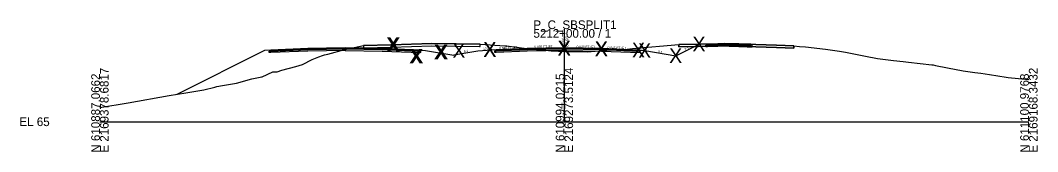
# Model space of a CAD drawing. Extents: x -26 to 1303, y -3010 to 12023.
# Drawn here: x 974.3 to 1302.8, y 7990.3 to 8032.8 of the extents above; entities that cross this region are included whole.
import ezdxf

# ---------------------------------------------------------------- set-up
doc = ezdxf.new("R2010")
doc.units = 0
for name, color, linetype in [('RD_GPK_XS_Cell', 7, 'Continuous'), ('RD_GPK_XS_Text_Node', 7, 'Continuous'), ('RD_XS_Base', 7, 'Continuous'), ('RD_XS_ExGround', 7, 'Continuous'), ('RD_XS_ExPaveRet', 7, 'Continuous'), ('RD_XS_Greenside', 7, 'Continuous'), ('RD_XS_Pave', 7, 'Continuous'), ('RD_XS_PaveOvlay_CP', 7, 'Continuous'), ('RD_XS_TieSlope', 7, 'Continuous'), ('RD_XS_TX_Elev_EX', 7, 'Continuous'), ('RD_XS_TX_Elev_PR', 7, 'Continuous'), ('RD_XS_TX_ShdSlope', 7, 'Continuous'), ('RD_XS_TX_Slope', 7, 'Continuous')]:
    doc.layers.add(name, color=color, linetype=linetype)

msp = doc.modelspace()

# ---------------------------------------------------------------- linework, layer by layer
at = {"layer": 'RD_GPK_XS_Cell'}
for p, q in [((1150, 8000), (1150, 8030)), ((1000, 8000), (1150, 8000)), ((1150, 8000), (1300, 8000))]:
    msp.add_line(p, q, dxfattribs=at)
at = {"layer": 'RD_XS_Base'}
for p, q in [((1054.69, 8022.87), (1055.18, 8022.89)), ((1054.69, 8022.86), (1054.69, 8022.87)), ((1054.69, 8022.37), (1054.69, 8022.86)), ((1055.18, 8022.89), (1055.19, 8022.89)), ((1055.19, 8022.89), (1067.13, 8023.37)), ((1067.13, 8022.87), (1055.19, 8022.39)), ((1067.13, 8023.37), (1067.19, 8023.37)), ((1067.19, 8022.87), (1067.13, 8022.87)), ((1067.19, 8023.37), (1079.18, 8023.61)), ((1079.18, 8023.11), (1067.19, 8022.87)), ((1079.18, 8023.61), (1079.18, 8023.77)), ((1079.18, 8023.77), (1079.18, 8023.11)), ((1079.18, 8023.61), (1079.19, 8023.61)), ((1079.18, 8023.61), (1079.18, 8023.11)), ((1091.18, 8023.37), (1079.18, 8023.61)), ((1079.18, 8023.61), (1079.18, 8023.61)), ((1079.19, 8023.11), (1079.18, 8023.11)), ((1079.18, 8023.11), (1079.18, 8023.11)), ((1079.18, 8023.11), (1079.18, 8023.11)), ((1079.18, 8023.11), (1091.18, 8022.87)), ((1079.19, 8023.61), (1079.19, 8023.77)), ((1079.19, 8023.77), (1079.19, 8023.77)), ((1079.19, 8023.77), (1079.19, 8023.77)), ((1079.19, 8023.77), (1079.19, 8023.11)), ((1079.19, 8023.61), (1079.19, 8023.61)), ((1079.19, 8023.61), (1079.19, 8023.11)), ((1079.2, 8023.61), (1079.19, 8023.61)), ((1079.19, 8023.11), (1079.2, 8023.11)), ((1103.18, 8022.89), (1091.18, 8023.37)), ((1091.18, 8022.87), (1103.68, 8022.37)), ((1093.18, 8023.29), (1093.18, 8023.29)), ((1093.18, 8022.79), (1093.18, 8022.79)), ((1103.68, 8022.87), (1103.18, 8022.89)), ((1103.18, 8022.89), (1103.18, 8022.89)), ((1103.68, 8022.37), (1103.68, 8022.87)), ((1103.68, 8022.87), (1103.68, 8022.87)), ((1127.5, 8022.95), (1128, 8022.97)), ((1127.5, 8022.45), (1127.5, 8022.95)), ((1127.5, 8022.95), (1127.5, 8022.95)), ((1128, 8022.97), (1138, 8023.37)), ((1128, 8022.97), (1128, 8022.97)), ((1138, 8022.87), (1128, 8022.47)), ((1136, 8023.29), (1136, 8023.29)), ((1136, 8022.79), (1136, 8022.79)), ((1138, 8023.37), (1150, 8023.61)), ((1150, 8023.11), (1138, 8022.87)), ((1150, 8023.61), (1150, 8023.77)), ((1150, 8023.77), (1150, 8023.11)), ((1150, 8023.61), (1150, 8023.11)), ((1150, 8023.61), (1150, 8023.61)), ((1162, 8023.37), (1150, 8023.61)), ((1150, 8023.61), (1150, 8023.61)), ((1150, 8023.11), (1150, 8023.11)), ((1150, 8023.11), (1150, 8023.11)), ((1150, 8023.11), (1162, 8022.87)), ((1174, 8022.89), (1162, 8023.37)), ((1162, 8023.37), (1162, 8023.37)), ((1162, 8022.87), (1162, 8022.87)), ((1162, 8022.87), (1174.5, 8022.37)), ((1174.5, 8022.87), (1174, 8022.89)), ((1174, 8022.89), (1174, 8022.89)), ((1174.5, 8022.37), (1174.5, 8022.87)), ((1174.5, 8022.87), (1174.5, 8022.87)), ((1195.67, 8024.77), (1196.17, 8024.78)), ((1195.67, 8024.27), (1195.67, 8024.77)), ((1196.17, 8024.28), (1195.67, 8024.27)), ((1196.17, 8024.78), (1198.17, 8024.82)), ((1198.17, 8024.32), (1196.17, 8024.28)), ((1198.17, 8024.82), (1203.17, 8024.92)), ((1203.17, 8024.42), (1198.17, 8024.32)), ((1203.17, 8024.98), (1203.17, 8025.08)), ((1203.17, 8025.08), (1203.17, 8024.67)), ((1203.17, 8024.92), (1203.17, 8024.98)), ((1206.35, 8024.85), (1203.17, 8024.92)), ((1203.17, 8024.92), (1203.17, 8024.42)), ((1203.17, 8024.67), (1203.17, 8024.42)), ((1203.17, 8024.42), (1206.35, 8024.36)), ((1208.17, 8024.82), (1206.35, 8024.85)), ((1206.35, 8024.36), (1208.17, 8024.32)), ((1208.89, 8024.8), (1208.17, 8024.82)), ((1208.17, 8024.32), (1209.07, 8024.3)), ((1210.17, 8024.78), (1208.89, 8024.8)), ((1209.07, 8024.3), (1210.67, 8024.27)), ((1210.35, 8024.78), (1210.17, 8024.78)), ((1210.67, 8024.77), (1210.35, 8024.78)), ((1210.67, 8024.44), (1210.67, 8024.77)), ((1210.67, 8024.27), (1210.67, 8024.44)), ((1055.18, 8022.39), (1054.69, 8022.37)), ((1055.19, 8022.39), (1055.18, 8022.39)), ((1103.68, 8022.37), (1103.68, 8022.37)), ((1103.68, 8022.37), (1103.68, 8022.37)), ((1128, 8022.47), (1127.5, 8022.45)), ((1127.5, 8022.45), (1127.5, 8022.45)), ((1127.5, 8022.45), (1127.5, 8022.45)), ((1128, 8022.47), (1128, 8022.47)), ((1174.5, 8022.37), (1174.5, 8022.37)), ((1174.5, 8022.37), (1174.5, 8022.37))]:
    msp.add_line(p, q, dxfattribs=at)
at = {"layer": 'RD_XS_ExGround'}
msp.add_lwpolyline([(1000, 8004.57), (1009.12, 8006.15), (1022.42, 8008.47), (1027.78, 8009.34), (1033.53, 8010.3), (1037.1, 8011.25), (1037.78, 8011.45), (1039.64, 8011.74), (1044.08, 8012.46), (1049.09, 8013.85), (1051.75, 8014.39), (1052.19, 8014.51), (1052.37, 8014.56), (1055.84, 8016.15), (1057.27, 8016.14), (1058.74, 8016.74), (1063.27, 8017.91), (1065.4, 8018.5), (1068.54, 8020.2), (1070.7, 8021.06), (1071.84, 8021.45), (1072.53, 8021.64), (1073.66, 8021.87), (1079.09, 8023.41), (1085.18, 8024.64), (1093.9, 8024.92), (1107.19, 8025.34), (1115, 8025.23), (1122.75, 8025.11), (1130.77, 8024.58), (1131.42, 8024.53), (1132.19, 8024.47), (1137.06, 8023.8), (1139.59, 8023.5), (1143.95, 8023.14), (1145.78, 8022.98), (1150.31, 8022.76), (1157.31, 8022.64), (1163.76, 8023.16), (1168.76, 8023.44), (1170.28, 8023.5), (1171.1, 8023.62), (1172.02, 8023.68), (1186.99, 8025.02), (1199.56, 8025.27), (1201.69, 8025.31), (1218.47, 8024.77), (1224.11, 8024.59), (1225.93, 8024.41), (1227.83, 8024.23), (1234.29, 8023.5), (1238.8, 8022.84), (1240.75, 8022.5), (1247.28, 8021.24), (1251.1, 8020.5), (1256.24, 8019.86), (1259.43, 8019.47), (1261.15, 8019.27), (1268.69, 8018.4), (1269.12, 8018.39), (1269.8, 8018.18), (1277.02, 8016.8), (1277.74, 8016.73), (1278.76, 8016.51), (1282.53, 8015.97), (1284.51, 8015.7), (1287.29, 8015.27), (1292.63, 8014.46), (1293.34, 8014.37), (1300, 8013.71)], dxfattribs=at)
at = {"layer": 'RD_XS_ExPaveRet'}
for points in [[(1122.75, 8025.11), (1122.75, 8025.11), (1122.58, 8025.11), (1115, 8025.23), (1114.73, 8025.24), (1107.19, 8025.34), (1094.09, 8024.93), (1093.9, 8024.92), (1085.2, 8024.64), (1085.18, 8024.64), (1085.18, 8024.64), (1085.18, 8023.89), (1085.2, 8023.89), (1093.9, 8024.17), (1094.09, 8024.18), (1107.19, 8024.59), (1114.73, 8024.49), (1115, 8024.48), (1122.58, 8024.36), (1122.75, 8024.36), (1122.75, 8024.36), (1122.75, 8024.36), (1122.75, 8025.09), (1122.75, 8025.11), (1122.75, 8025.11)], [(1122.75, 8025.11), (1122.75, 8025.11), (1122.58, 8025.11), (1115, 8025.23), (1114.73, 8025.24), (1107.19, 8025.34), (1094.09, 8024.93), (1093.9, 8024.92), (1085.2, 8024.64), (1085.18, 8024.64), (1085.18, 8024.64), (1085.18, 8023.89), (1085.2, 8023.89), (1093.9, 8024.17), (1094.09, 8024.18), (1107.19, 8024.59), (1114.73, 8024.49), (1115, 8024.48), (1122.58, 8024.36), (1122.75, 8024.36), (1122.75, 8024.36), (1122.75, 8025.09), (1122.75, 8025.11)], [(1224.11, 8024.59), (1224.11, 8023.84), (1224.11, 8023.84), (1224.11, 8023.84), (1224.11, 8023.84), (1218.47, 8024.02), (1218.47, 8024.02), (1201.69, 8024.56), (1201.69, 8024.56), (1199.56, 8024.52), (1199.56, 8024.52), (1186.99, 8024.27), (1186.99, 8024.27), (1186.99, 8025.02), (1199.56, 8025.27), (1199.56, 8025.27), (1201.69, 8025.31), (1201.69, 8025.31), (1218.47, 8024.77), (1218.47, 8024.77), (1224.11, 8024.59), (1224.11, 8024.59), (1224.11, 8024.59)], [(1224.11, 8024.59), (1218.47, 8024.77), (1201.69, 8025.31), (1199.56, 8025.27), (1186.99, 8025.02), (1186.99, 8024.27), (1199.56, 8024.52), (1201.69, 8024.56), (1218.47, 8024.02), (1224.11, 8023.84), (1224.11, 8023.84), (1224.11, 8024.59), (1224.11, 8024.59)]]:
    msp.add_lwpolyline(points, dxfattribs=at)
at = {"layer": 'RD_XS_Greenside'}
for p, q in [((1053.19, 8023.05), (1024.8, 8008.85)), ((1105.18, 8023.05), (1114.31, 8021.52)), ((1122, 8022.81), (1114.31, 8021.52)), ((1176, 8023.05), (1186, 8021.38)), ((1186, 8021.38), (1193.55, 8025.15))]:
    msp.add_line(p, q, dxfattribs=at)
at = {"layer": 'RD_XS_Pave'}
for p, q in [((1067.13, 8023.68), (1055.19, 8023.21)), ((1067.13, 8023.52), (1055.19, 8023.05)), ((1055.19, 8023.05), (1067.13, 8023.52)), ((1055.19, 8022.89), (1067.13, 8023.37)), ((1055.19, 8023.21), (1055.19, 8023.2)), ((1055.19, 8023.2), (1055.19, 8023.05)), ((1055.19, 8023.05), (1055.19, 8023.05)), ((1055.19, 8023.05), (1055.19, 8022.89)), ((1067.19, 8023.69), (1067.13, 8023.68)), ((1067.19, 8023.53), (1067.13, 8023.52)), ((1067.13, 8023.52), (1067.19, 8023.53)), ((1067.13, 8023.37), (1067.19, 8023.37)), ((1079.18, 8023.93), (1067.19, 8023.69)), ((1079.18, 8023.77), (1067.19, 8023.53)), ((1067.19, 8023.53), (1079.18, 8023.77)), ((1067.19, 8023.37), (1079.18, 8023.61)), ((1079.19, 8023.93), (1079.18, 8023.93)), ((1091.18, 8023.69), (1079.18, 8023.93)), ((1079.19, 8023.77), (1079.18, 8023.77)), ((1079.18, 8023.77), (1079.19, 8023.77)), ((1079.18, 8023.61), (1079.18, 8023.77)), ((1079.18, 8023.77), (1091.18, 8023.53)), ((1091.18, 8023.53), (1079.18, 8023.77)), ((1079.18, 8023.77), (1079.18, 8023.61)), ((1079.18, 8023.61), (1079.19, 8023.61)), ((1079.18, 8023.61), (1079.18, 8023.61)), ((1079.18, 8023.61), (1079.18, 8023.61)), ((1079.18, 8023.61), (1091.18, 8023.37)), ((1079.2, 8023.93), (1079.19, 8023.93)), ((1079.19, 8023.61), (1079.19, 8023.77)), ((1079.19, 8023.77), (1079.19, 8023.77)), ((1079.19, 8023.77), (1079.2, 8023.77)), ((1079.2, 8023.77), (1079.19, 8023.77)), ((1079.19, 8023.77), (1079.19, 8023.77)), ((1079.19, 8023.77), (1079.19, 8023.61)), ((1079.19, 8023.61), (1079.2, 8023.61)), ((1103.18, 8023.21), (1091.18, 8023.69)), ((1091.18, 8023.53), (1103.18, 8023.05)), ((1103.18, 8023.05), (1091.18, 8023.53)), ((1091.18, 8023.37), (1103.18, 8022.89)), ((1093.18, 8023.61), (1093.18, 8023.61)), ((1093.18, 8023.45), (1093.18, 8023.45)), ((1093.18, 8023.45), (1093.18, 8023.45)), ((1093.18, 8023.29), (1093.18, 8023.29)), ((1103.18, 8023.05), (1103.18, 8023.21)), ((1103.18, 8023.21), (1103.18, 8023.21)), ((1103.18, 8023.05), (1103.18, 8023.05)), ((1103.18, 8023.05), (1103.18, 8023.05)), ((1103.18, 8022.89), (1103.18, 8023.05)), ((1103.18, 8023.05), (1103.18, 8023.05)), ((1103.18, 8022.89), (1103.18, 8022.89)), ((1103.18, 8022.89), (1103.18, 8022.89)), ((1138, 8023.69), (1128, 8023.29)), ((1138, 8023.53), (1128, 8023.13)), ((1128, 8023.13), (1138, 8023.53)), ((1128, 8022.97), (1138, 8023.37)), ((1128, 8023.29), (1128, 8023.29)), ((1128, 8023.29), (1128, 8023.13)), ((1128, 8023.13), (1128, 8023.13)), ((1128, 8023.13), (1128, 8022.97)), ((1128, 8023.13), (1128, 8023.13)), ((1128, 8023.13), (1128, 8023.13)), ((1128, 8022.97), (1128, 8022.97)), ((1128, 8022.97), (1128, 8022.97)), ((1136, 8023.61), (1136, 8023.61)), ((1136, 8023.45), (1136, 8023.45)), ((1136, 8023.45), (1136, 8023.45)), ((1136, 8023.29), (1136, 8023.29)), ((1150, 8023.93), (1138, 8023.69)), ((1150, 8023.77), (1138, 8023.53)), ((1138, 8023.53), (1150, 8023.77)), ((1138, 8023.37), (1150, 8023.61)), ((1162, 8023.69), (1150, 8023.93)), ((1150, 8023.61), (1150, 8023.77)), ((1150, 8023.77), (1162, 8023.53)), ((1162, 8023.53), (1150, 8023.77)), ((1150, 8023.77), (1150, 8023.77)), ((1150, 8023.77), (1150, 8023.61)), ((1150, 8023.61), (1150, 8023.61)), ((1150, 8023.61), (1150, 8023.61)), ((1150, 8023.61), (1150, 8023.61)), ((1150, 8023.61), (1162, 8023.37)), ((1174, 8023.21), (1162, 8023.69)), ((1162, 8023.69), (1162, 8023.69)), ((1162, 8023.53), (1162, 8023.53)), ((1162, 8023.53), (1174, 8023.05)), ((1174, 8023.05), (1162, 8023.53)), ((1162, 8023.53), (1162, 8023.53)), ((1162, 8023.37), (1162, 8023.37)), ((1162, 8023.37), (1174, 8022.89)), ((1174, 8023.05), (1174, 8023.21)), ((1174, 8023.21), (1174, 8023.21)), ((1174, 8023.05), (1174, 8023.05)), ((1174, 8023.05), (1174, 8023.05)), ((1174, 8022.89), (1174, 8023.05)), ((1174, 8023.05), (1174, 8023.05)), ((1174, 8022.89), (1174, 8022.89)), ((1174, 8022.89), (1174, 8022.89)), ((1196.96, 8025.11), (1196.17, 8025.1)), ((1196.17, 8025.1), (1196.17, 8025)), ((1196.17, 8025), (1196.17, 8024.94)), ((1198.17, 8024.98), (1196.17, 8024.94)), ((1196.17, 8024.94), (1196.96, 8024.95)), ((1196.17, 8024.94), (1196.17, 8024.78)), ((1196.17, 8024.78), (1198.17, 8024.82)), ((1198.17, 8025.14), (1196.96, 8025.11)), ((1196.96, 8024.95), (1198.17, 8024.98)), ((1201.27, 8025.2), (1198.17, 8025.14)), ((1203.17, 8025.08), (1198.17, 8024.98)), ((1198.17, 8024.98), (1201.27, 8025.04)), ((1198.17, 8024.82), (1203.17, 8024.92)), ((1203.17, 8025.24), (1201.27, 8025.2)), ((1201.27, 8025.04), (1203.17, 8025.08)), ((1206.35, 8025.17), (1203.17, 8025.24)), ((1203.17, 8025.08), (1206.35, 8025.01)), ((1208.17, 8024.98), (1203.17, 8025.08)), ((1203.17, 8025.08), (1203.17, 8024.92)), ((1203.17, 8024.92), (1203.17, 8025.08)), ((1203.17, 8024.92), (1208.17, 8024.82)), ((1208.17, 8025.14), (1206.35, 8025.17)), ((1206.35, 8025.01), (1208.17, 8024.98)), ((1208.89, 8025.12), (1208.17, 8025.14)), ((1208.17, 8024.98), (1208.89, 8024.96)), ((1210.17, 8024.94), (1208.17, 8024.98)), ((1208.17, 8024.82), (1210.17, 8024.78)), ((1210.17, 8025.1), (1208.89, 8025.12)), ((1208.89, 8024.96), (1210.17, 8024.94)), ((1210.17, 8024.99), (1210.17, 8025.1)), ((1210.17, 8024.94), (1210.17, 8024.99)), ((1210.17, 8024.78), (1210.17, 8024.94))]:
    msp.add_line(p, q, dxfattribs=at)
at = {"layer": 'RD_XS_PaveOvlay_CP'}
for p, q in [((1055.19, 8023.21), (1067.19, 8023.69)), ((1067.19, 8023.69), (1079.19, 8023.93)), ((1079.18, 8023.93), (1091.18, 8023.69)), ((1091.18, 8023.69), (1103.18, 8023.21)), ((1138, 8023.69), (1128, 8023.29)), ((1128, 8023.29), (1128, 8023.29)), ((1136, 8023.61), (1136, 8023.61)), ((1150, 8023.93), (1138, 8023.69)), ((1162, 8023.69), (1150, 8023.93)), ((1174, 8023.21), (1162, 8023.69)), ((1162, 8023.69), (1162, 8023.69)), ((1174, 8023.21), (1174, 8023.21)), ((1196.17, 8025.1), (1198.17, 8025.14)), ((1198.17, 8025.14), (1203.17, 8025.24)), ((1203.17, 8025.24), (1208.17, 8025.14)), ((1208.17, 8025.14), (1210.17, 8025.1))]:
    msp.add_line(p, q, dxfattribs=at)
at = {"layer": 'RD_XS_TieSlope'}
for p, q in [((1055.19, 8023.21), (1053.19, 8023.05)), ((1103.18, 8023.21), (1105.18, 8023.05)), ((1128, 8023.29), (1122, 8022.81)), ((1174, 8023.21), (1176, 8023.05))]:
    msp.add_line(p, q, dxfattribs=at)

# ---------------------------------------------------------------- texts
at = {"layer": 'RD_GPK_XS_Cell'}
for s, p in [('P_C_SBSPLIT1', (1140, 8030)), ('5212+00.00 / 1', (1140, 8027.2)), ('EL 65', (974, 7998.6))]:
    msp.add_text(s, height=2.8, dxfattribs=at).set_placement(p)
for s, p in [('E 2169378.6817', (1002.8, 7990)), ('E 2169273.5124', (1152.8, 7990)), ('E 2169168.3432', (1302.8, 7990)), ('N 610887.0662', (1000, 7990)), ('N 610994.0215', (1150, 7990)), ('N 611100.9768', (1300, 7990))]:
    msp.add_text(s, height=2.8, rotation=90, dxfattribs=at).set_placement(p)
at = {"layer": 'RD_GPK_XS_Text_Node'}
for p in [(1092.42, 8022.6), (1092.89, 8022.6), (1147.84, 8021.58), (1147.84, 8021.42), (1191.38, 8022.81), (1099.84, 8018.89), (1100.32, 8018.89), (1107.84, 8020.22), (1108.32, 8020.22), (1113.84, 8020.7), (1123.84, 8021.1), (1123.84, 8020.94), (1159.84, 8021.34), (1159.84, 8021.18), (1171.84, 8020.86), (1173.84, 8020.7), (1183.84, 8019.04)]:
    msp.add_text('X', height=4.69, dxfattribs=at).set_placement(p)
at = {"layer": 'RD_XS_TX_Elev_EX'}
msp.add_text('87.80', height=0.6, rotation=90, dxfattribs=at).set_placement((1149.67, 8024.85))
at = {"layer": 'RD_XS_TX_Elev_PR'}
msp.add_text('88.93', height=1, rotation=90, dxfattribs=at).set_placement((1151.27, 8024.26))
at = {"layer": 'RD_XS_TX_ShdSlope'}
for rotation, p in [(4.5739, (1123.78, 8023.23)), (355.4261, (1173.71, 8023.43))]:
    msp.add_text('12.5:1', height=0.75, rotation=rotation, dxfattribs=at).set_placement(p)
at = {"layer": 'RD_XS_TX_Slope'}
for s, rotation, p in [('6:1', 9.4642, (1117.6, 8022.42)), ('0.040 FT./FT.', 2.2906, (1128.93, 8023.42)), ('0.020 FT./FT.', 1.1458, (1140.27, 8023.9)), ('0.020 FT./FT.', 358.8542, (1153.94, 8023.94)), ('0.040 FT./FT.', 357.7094, (1163.94, 8023.71)), ('6:1', 350.5358, (1180.2, 8022.4)), ('2:1', 26.5651, (1189.05, 8022.96))]:
    msp.add_text(s, height=0.75, rotation=rotation, dxfattribs=at).set_placement(p)

doc.saveas('drawing.dxf')
